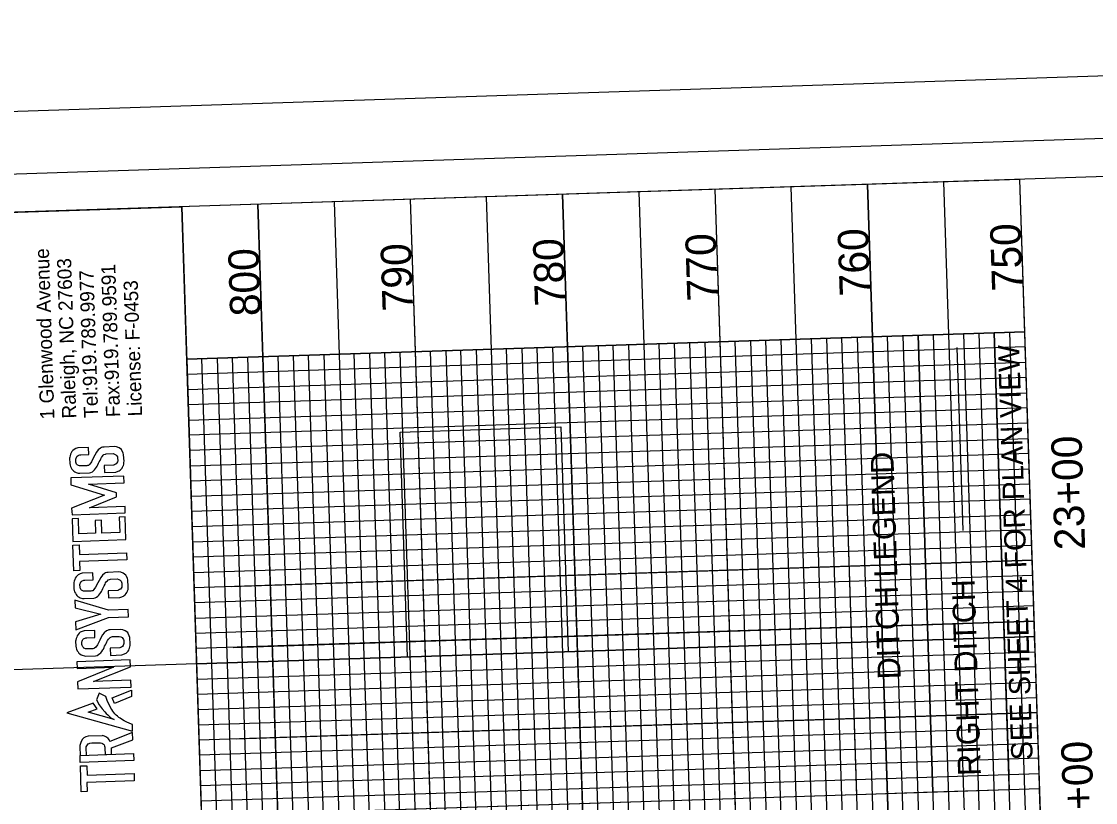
# Model space of a CAD drawing. Extents: x 1627314 to 1628469, y 762309 to 764212.
# Drawn here: x 1627512.6 to 1627864.9, y 763788.2 to 764044.4 of the extents above; entities that cross this region are included whole.
import ezdxf

# ---------------------------------------------------------------- set-up
doc = ezdxf.new("R2010")
doc.units = 0
for name, color, linetype in [('Exist Vertical Profile Horizontal Axis Label Major', 7, 'Continuous'), ('Exist Vertical Profile Vertical Axis Label', 7, 'Continuous'), ('Old_Level_2', 7, 'Continuous'), ('Old_Level_58', 7, 'Continuous'), ('Prop DSN Text', 7, 'Continuous'), ('Prop Grid Mask', 7, 'Continuous'), ('Prop PFL Ditch Label CELL', 7, 'Continuous'), ('Sheet DOT Grid CELL', 7, 'Continuous'), ('Sheet Layout Profile Border Port 1', 7, 'Continuous'), ('Sheet Plot Border Inside CELL', 7, 'Continuous'), ('Sheet Plot Border Outside CELL', 7, 'Continuous'), ('Sheet Profile CELL', 7, 'Continuous'), ('Sheet Profile Grid Major CELL', 7, 'Continuous'), ('Sheet Profile Grid Middle CELL', 7, 'Continuous'), ('Sheet Profile Grid Minor CELL', 7, 'Continuous')]:
    doc.layers.add(name, color=color, linetype=linetype)

msp = doc.modelspace()

# ---------------------------------------------------------------- linework, layer by layer
at = {"layer": 'Old_Level_2'}
for points in [[(1627534.7, 763902.32), (1627534.62, 763904.63), (1627531.15, 763904.51), (1627530.45, 763904.29), (1627529.87, 763903.99), (1627529.49, 763903.68), (1627529.15, 763903.3), (1627528.88, 763902.85), (1627528.72, 763902.42), (1627528.72, 763902.42), (1627528.54, 763901.95), (1627528.44, 763901.47), (1627528.37, 763901.14), (1627528.46, 763899.4), (1627528.57, 763898.87), (1627528.66, 763898.42), (1627528.92, 763897.96), (1627529.14, 763897.57), (1627529.44, 763897.18), (1627529.76, 763896.88), (1627530.13, 763896.65), (1627530.53, 763896.47), (1627531.24, 763896.24), (1627531.76, 763896.2), (1627534.92, 763896.31), (1627535.4, 763896.44), (1627535.88, 763896.68), (1627536.28, 763896.99), (1627536.58, 763897.29), (1627536.92, 763897.76), (1627537.25, 763898.22), (1627537.46, 763898.51), (1627537.67, 763899), (1627537.88, 763899.49), (1627538.12, 763899.89), (1627538.39, 763900.34), (1627538.64, 763900.87), (1627538.84, 763901.31), (1627539.14, 763901.75), (1627539.43, 763902.07), (1627539.66, 763902.33), (1627540.13, 763902.5), (1627540.43, 763902.6), (1627542.67, 763902.64), (1627543.16, 763902.5), (1627543.58, 763902.27), (1627543.88, 763901.95), (1627544.06, 763901.6), (1627544.14, 763901.26), (1627544.19, 763900.3), (1627544.11, 763899.97), (1627543.93, 763899.64), (1627543.75, 763899.3), (1627543.42, 763899.15), (1627543.09, 763899), (1627542.82, 763898.88), (1627539.71, 763898.74), (1627539.82, 763896.4), (1627543.52, 763896.57), (1627543.8, 763896.69), (1627544.65, 763896.99), (1627544.94, 763897.18), (1627545.25, 763897.44), (1627545.61, 763897.83), (1627545.8, 763898.14), (1627545.96, 763898.58), (1627546.03, 763898.74), (1627546.19, 763899.18), (1627546.23, 763899.72), (1627546.25, 763900.11), (1627546.13, 763902.25), (1627545.97, 763902.84), (1627545.57, 763903.65), (1627545.43, 763903.93), (1627544.62, 763904.52), (1627543.83, 763904.83), (1627543.11, 763904.96), (1627539.69, 763904.8), (1627539.22, 763904.77), (1627538.85, 763904.63), (1627538.5, 763904.43), (1627537.76, 763903.86), (1627537.23, 763903.14), (1627536.68, 763902.14), (1627536.26, 763901.39), (1627535.54, 763899.9), (1627535.01, 763899.13), (1627534.59, 763898.78), (1627534.31, 763898.7), (1627534.03, 763898.61), (1627531.6, 763898.58), (1627531.34, 763898.69), (1627531.08, 763898.81), (1627530.93, 763898.98), (1627530.72, 763899.21), (1627530.61, 763899.46), (1627530.49, 763899.72), (1627530.52, 763899.86), (1627530.44, 763899.88), (1627530.42, 763900.84), (1627530.53, 763901.12), (1627530.63, 763901.4), (1627530.73, 763901.68), (1627530.91, 763901.81), (1627531.19, 763902.01), (1627531.46, 763902.11), (1627531.73, 763902.21), (1627532.04, 763902.21)], [(1627539.83, 763888.95), (1627529.04, 763884.78), (1627529.22, 763882.58), (1627546.67, 763883.23), (1627546.59, 763885.34), (1627534.92, 763884.9), (1627543.79, 763888.46), (1627543.78, 763889.81), (1627534.56, 763892.58), (1627546.27, 763893), (1627546.19, 763895.28), (1627528.78, 763894.65), (1627528.86, 763892.35)], [(1627529.23, 763881.22), (1627529.48, 763873.84), (1627546.89, 763874.43), (1627546.64, 763881.9), (1627544.67, 763881.83), (1627544.84, 763876.79), (1627539, 763876.59), (1627538.86, 763880.8), (1627536.79, 763880.73), (1627536.93, 763876.49), (1627531.44, 763876.3), (1627531.27, 763881.31)], [(1627529.79, 763864.16), (1627529.51, 763872.62), (1627531.58, 763872.69), (1627531.69, 763869.58), (1627547.1, 763870.1), (1627547.18, 763867.75), (1627531.66, 763867.23), (1627531.76, 763864.26)], [(1627536.08, 763861.21), (1627536.01, 763863.52), (1627532.53, 763863.4), (1627531.83, 763863.18), (1627531.25, 763862.88), (1627530.87, 763862.57), (1627530.53, 763862.19), (1627530.26, 763861.74), (1627530.1, 763861.31), (1627530.1, 763861.31), (1627529.93, 763860.84), (1627529.82, 763860.36), (1627529.75, 763860.03), (1627529.84, 763858.29), (1627529.95, 763857.76), (1627530.04, 763857.31), (1627530.3, 763856.85), (1627530.52, 763856.46), (1627530.82, 763856.07), (1627531.14, 763855.77), (1627531.52, 763855.54), (1627531.92, 763855.36), (1627532.62, 763855.13), (1627533.14, 763855.09), (1627536.31, 763855.2), (1627536.78, 763855.33), (1627537.26, 763855.58), (1627537.67, 763855.88), (1627537.97, 763856.18), (1627538.3, 763856.65), (1627538.63, 763857.11), (1627538.84, 763857.4), (1627539.05, 763857.89), (1627539.26, 763858.38), (1627539.5, 763858.78), (1627539.77, 763859.23), (1627540.02, 763859.77), (1627540.23, 763860.21), (1627540.53, 763860.65), (1627540.81, 763860.96), (1627541.04, 763861.22), (1627541.52, 763861.39), (1627541.81, 763861.5), (1627544.05, 763861.53), (1627544.54, 763861.39), (1627544.97, 763861.16), (1627545.27, 763860.84), (1627545.44, 763860.49), (1627545.52, 763860.15), (1627545.57, 763859.19), (1627545.49, 763858.87), (1627545.31, 763858.53), (1627545.13, 763858.2), (1627544.8, 763858.04), (1627544.47, 763857.89), (1627544.21, 763857.77), (1627541.1, 763857.63), (1627541.2, 763855.29), (1627544.91, 763855.46), (1627545.19, 763855.58), (1627546.04, 763855.88), (1627546.32, 763856.07), (1627546.63, 763856.33), (1627547, 763856.72), (1627547.18, 763857.03), (1627547.35, 763857.48), (1627547.41, 763857.64), (1627547.58, 763858.07), (1627547.61, 763858.61), (1627547.64, 763859), (1627547.51, 763861.14), (1627547.35, 763861.73), (1627546.95, 763862.54), (1627546.82, 763862.82), (1627546.01, 763863.41), (1627545.21, 763863.72), (1627544.49, 763863.85), (1627541.08, 763863.69), (1627540.6, 763863.66), (1627540.23, 763863.52), (1627539.88, 763863.32), (1627539.14, 763862.75), (1627538.61, 763862.03), (1627538.06, 763861.04), (1627537.64, 763860.28), (1627536.92, 763858.79), (1627536.39, 763858.02), (1627535.98, 763857.67), (1627535.7, 763857.59), (1627535.42, 763857.5), (1627532.98, 763857.47), (1627532.73, 763857.58), (1627532.47, 763857.7), (1627532.31, 763857.87), (1627532.11, 763858.1), (1627531.99, 763858.35), (1627531.87, 763858.61), (1627531.9, 763858.75), (1627531.82, 763858.77), (1627531.81, 763859.73), (1627531.91, 763860.01), (1627532.01, 763860.29), (1627532.11, 763860.57), (1627532.3, 763860.7), (1627532.57, 763860.9), (1627532.84, 763861), (1627533.12, 763861.1), (1627533.42, 763861.1)], [(1627530.37, 763847.41), (1627530.45, 763844.88), (1627541.21, 763848.85), (1627547.75, 763849.09), (1627547.66, 763851.48), (1627541.17, 763851.24), (1627530.09, 763854.54), (1627530.24, 763852.05), (1627538.66, 763850.01)], [(1627536.72, 763842.35), (1627536.64, 763844.65), (1627533.16, 763844.54), (1627532.47, 763844.32), (1627531.89, 763844.02), (1627531.51, 763843.71), (1627531.17, 763843.33), (1627530.9, 763842.88), (1627530.74, 763842.45), (1627530.74, 763842.45), (1627530.56, 763841.98), (1627530.45, 763841.5), (1627530.38, 763841.17), (1627530.48, 763839.43), (1627530.59, 763838.9), (1627530.68, 763838.45), (1627530.93, 763837.99), (1627531.16, 763837.6), (1627531.46, 763837.21), (1627531.78, 763836.91), (1627532.15, 763836.68), (1627532.55, 763836.5), (1627533.26, 763836.27), (1627533.77, 763836.23), (1627536.94, 763836.34), (1627537.41, 763836.47), (1627537.9, 763836.71), (1627538.3, 763837.02), (1627538.6, 763837.32), (1627538.93, 763837.78), (1627539.27, 763838.25), (1627539.48, 763838.54), (1627539.69, 763839.03), (1627539.89, 763839.52), (1627540.13, 763839.92), (1627540.41, 763840.37), (1627540.66, 763840.9), (1627540.86, 763841.34), (1627541.16, 763841.78), (1627541.45, 763842.1), (1627541.68, 763842.36), (1627542.15, 763842.53), (1627542.45, 763842.63), (1627544.68, 763842.67), (1627545.17, 763842.53), (1627545.6, 763842.3), (1627545.9, 763841.98), (1627546.07, 763841.63), (1627546.16, 763841.29), (1627546.21, 763840.33), (1627546.13, 763840), (1627545.95, 763839.67), (1627545.76, 763839.33), (1627545.43, 763839.18), (1627545.1, 763839.03), (1627544.84, 763838.91), (1627541.73, 763838.77), (1627541.84, 763836.43), (1627545.54, 763836.6), (1627545.82, 763836.72), (1627546.67, 763837.02), (1627546.96, 763837.21), (1627547.27, 763837.47), (1627547.63, 763837.86), (1627547.81, 763838.17), (1627547.98, 763838.61), (1627548.04, 763838.77), (1627548.21, 763839.21), (1627548.25, 763839.75), (1627548.27, 763840.14), (1627548.15, 763842.28), (1627547.99, 763842.87), (1627547.59, 763843.68), (1627547.45, 763843.95), (1627546.64, 763844.55), (1627545.84, 763844.86), (1627545.13, 763844.99), (1627541.71, 763844.83), (1627541.24, 763844.8), (1627540.87, 763844.66), (1627540.52, 763844.46), (1627539.78, 763843.89), (1627539.24, 763843.17), (1627538.7, 763842.17), (1627538.28, 763841.42), (1627537.56, 763839.93), (1627537.02, 763839.15), (1627536.61, 763838.81), (1627536.33, 763838.73), (1627536.05, 763838.64), (1627533.62, 763838.61), (1627533.36, 763838.72), (1627533.1, 763838.84), (1627532.94, 763839.01), (1627532.74, 763839.23), (1627532.62, 763839.49), (1627532.51, 763839.75), (1627532.53, 763839.89), (1627532.46, 763839.91), (1627532.44, 763840.86), (1627532.54, 763841.15), (1627532.64, 763841.43), (1627532.74, 763841.71), (1627532.93, 763841.84), (1627533.2, 763842.04), (1627533.48, 763842.14), (1627533.75, 763842.24), (1627534.06, 763842.24)], [(1627531.1, 763825.45), (1627548.55, 763826.04), (1627548.47, 763828.28), (1627536.2, 763827.86), (1627548.35, 763832.72), (1627548.25, 763834.96), (1627530.75, 763834.37), (1627530.83, 763832.19), (1627542.8, 763832.6), (1627531.01, 763827.81)], [(1627527.54, 763817.56), (1627549.08, 763811.6), (1627548.99, 763813.82), (1627548.14, 763814.14), (1627546.97, 763814.67), (1627546.33, 763814.96), (1627545.78, 763815.32), (1627545, 763815.82), (1627544.52, 763816.13), (1627544.12, 763816.5), (1627543.71, 763816.86), (1627543.2, 763817.33), (1627542.92, 763817.74), (1627542.57, 763818.14), (1627542.23, 763818.69), (1627541.93, 763819.17), (1627541.33, 763820.37), (1627540.88, 763821.35), (1627540.27, 763822.98), (1627538.09, 763824.04), (1627537.21, 763821.84), (1627538.15, 763820.23), (1627539.1, 763818.89), (1627539.92, 763817.93), (1627540.37, 763817.42), (1627540.95, 763816.91), (1627541.54, 763816.39), (1627541.97, 763816.01), (1627542.63, 763815.65), (1627543, 763815.45), (1627534.54, 763817.81), (1627537.4, 763818.9), (1627536.08, 763820.75)], [(1627543.15, 763820.69), (1627542.32, 763822.58), (1627548.68, 763825.05), (1627548.67, 763822.95)], [(1627533.93, 763803.74), (1627533.85, 763806.13), (1627533.89, 763806.43), (1627534.04, 763806.84), (1627534.24, 763807.17), (1627534.51, 763807.41), (1627534.83, 763807.58), (1627535.09, 763807.71), (1627535.67, 763807.73), (1627538.16, 763807.82), (1627538.49, 763807.77), (1627538.94, 763807.7), (1627539.23, 763807.58), (1627539.5, 763807.38), (1627539.72, 763807.12), (1627539.89, 763806.7), (1627539.94, 763806.38), (1627539.99, 763806.05), (1627540.07, 763803.95), (1627542.18, 763804.03), (1627542.1, 763806.13), (1627549.18, 763808.74), (1627549.07, 763811.15), (1627541.63, 763808.25), (1627541.48, 763808.63), (1627541.06, 763809.15), (1627540.51, 763809.62), (1627539.87, 763809.95), (1627539.23, 763810.14), (1627539.04, 763810.12), (1627534.48, 763810.01), (1627533.74, 763809.79), (1627533.08, 763809.4), (1627532.62, 763808.98), (1627532.17, 763808.26), (1627531.96, 763807.58), (1627531.76, 763806.89), (1627531.77, 763806.49), (1627531.84, 763803.67)], [(1627531.92, 763801.36), (1627531.84, 763803.67), (1627549.4, 763804.26), (1627549.48, 763801.95)], [(1627532.23, 763791.74), (1627531.95, 763800.2), (1627534.02, 763800.27), (1627534.12, 763797.16), (1627549.54, 763797.68), (1627549.62, 763795.33), (1627534.1, 763794.81), (1627534.2, 763791.84)]]:
    msp.add_lwpolyline(points, close=True, dxfattribs=at)
at = {"layer": 'Old_Level_58'}
msp.add_lwpolyline([(1627507.79, 763781.55), (1627501.25, 763981.49), (1627565.16, 763983.58), (1627571.7, 763783.64)], close=True, dxfattribs=at)
at = {"layer": 'Prop Grid Mask'}
for points in [[(1627811.57, 763791.55), (1627806.67, 763941.47), (1627831.66, 763942.29), (1627836.56, 763792.37)], [(1627831.66, 763942.29), (1627836.4, 763797.36), (1627846.39, 763797.69), (1627841.65, 763942.61)], [(1627786.59, 763790.73), (1627781.68, 763940.65), (1627806.67, 763941.47), (1627811.57, 763791.55)], [(1627639.21, 763835.85), (1627636.79, 763909.68), (1627689.5, 763911.4), (1627691.91, 763837.57)]]:
    msp.add_lwpolyline(points, close=True, dxfattribs=at)
at = {"layer": 'Prop PFL Ditch Label CELL'}
for p, q in [((1627821.42, 763877.47), (1627819.46, 763937.43)), ((1627821.42, 763877.47), (1627819.46, 763937.43)), ((1627826.56, 763792.04), (1627826.56, 763792.04))]:
    msp.add_line(p, q, dxfattribs=at)
at = {"layer": 'Sheet DOT Grid CELL'}
for p, q in [((1627740.07, 763989.32), (1627789.11, 762490.12)), ((1627790.04, 763990.95), (1627839.08, 762491.75)), ((1627590.15, 763984.41), (1627639.19, 762485.21)), ((1627640.12, 763986.05), (1627689.16, 762486.85)), ((1627690.1, 763987.68), (1627739.13, 762488.48)), ((1627841.65, 763942.61), (1627566.8, 763933.62)), ((1627843.28, 763892.64), (1627568.43, 763883.65)), ((1627844.92, 763842.67), (1627570.07, 763833.68)), ((1627846.55, 763792.69), (1627484.3, 763780.84))]:
    msp.add_line(p, q, dxfattribs=at)
at = {"layer": 'Sheet Layout Profile Border Port 1'}
msp.add_lwpolyline([(1627386.05, 762576.99), (1627885.78, 762593.33), (1627841.65, 763942.61), (1627566.8, 763933.62), (1627570.07, 763833.63), (1627345.19, 763826.32)], close=True, dxfattribs=at)
msp.add_lwpolyline([(1627548.65, 762532.28), (1627887.42, 762543.36), (1627841.65, 763942.61), (1627566.8, 763933.62)], dxfattribs=at)
at = {"layer": 'Sheet Plot Border Inside CELL'}
msp.add_lwpolyline([(1628446.34, 762357.53), (1628391.86, 764023.14), (1627337.33, 763988.65), (1627391.81, 762323.04)], close=True, dxfattribs=at)
at = {"layer": 'Sheet Plot Border Outside CELL'}
msp.add_lwpolyline([(1628469.21, 762345.27), (1628413.63, 764044.37), (1627314.22, 764008.4), (1627369.79, 762309.31)], close=True, dxfattribs=at)
at = {"layer": 'Sheet Profile CELL'}
msp.add_line((1627889.05, 762493.39), (1627840.02, 763992.59), dxfattribs=at)
msp.add_lwpolyline([(1627340.28, 763976.24), (1627389.32, 762477.04), (1628438.76, 762511.37), (1628389.72, 764010.57)], close=True, dxfattribs=at)
at = {"layer": 'Sheet Profile Grid Major CELL'}
for points in [[(1627566.8, 763933.62), (1627841.65, 763942.61), (1627840.02, 763992.59), (1627490.2, 763981.14)], [(1627740.07, 763989.32), (1627789.11, 762490.12), (1627789.11, 762490.12), (1627839.08, 762491.75), (1627790.04, 763990.95)], [(1627546.71, 763782.88), (1627589.21, 762483.58), (1627639.19, 762485.21), (1627590.15, 763984.41)], [(1627640.12, 763986.05), (1627689.16, 762486.85), (1627739.13, 762488.48), (1627690.1, 763987.68)], [(1627570.07, 763833.68), (1627844.92, 763842.67), (1627843.28, 763892.64), (1627843.28, 763892.64), (1627568.43, 763883.65)], [(1627861.27, 763342.93), (1627859.63, 763392.91), (1627359.9, 763376.56), (1627358.26, 763426.53), (1627858, 763442.88), (1627856.36, 763492.85), (1627356.63, 763476.51), (1627354.99, 763526.48), (1627854.73, 763542.83), (1627853.09, 763592.8), (1627353.36, 763576.45), (1627351.73, 763626.43), (1627851.46, 763642.77), (1627849.82, 763692.75), (1627350.09, 763676.4), (1627348.46, 763726.37), (1627848.19, 763742.72), (1627846.55, 763792.69), (1627346.82, 763776.35), (1627345.96, 763802.63)]]:
    msp.add_lwpolyline(points, dxfattribs=at)
at = {"layer": 'Sheet Profile Grid Middle CELL'}
for points in [[(1627815.03, 763991.77), (1627864.07, 762492.57)], [(1627715.08, 763988.5), (1627764.12, 762489.3), (1627814.09, 762490.94), (1627765.06, 763990.13)], [(1627615.14, 763985.23), (1627664.17, 762486.03), (1627714.15, 762487.67), (1627665.11, 763986.86)], [(1627570.88, 763808.69), (1627565.16, 763983.6)], [(1627581.44, 763859.06), (1627844.1, 763867.65), (1627842.47, 763917.63), (1627567.61, 763908.64)], [(1627583.08, 763809.09), (1627845.74, 763817.68), (1627844.1, 763867.65), (1627569.25, 763858.66)], [(1627360.72, 763351.57), (1627860.45, 763367.92), (1627858.81, 763417.89), (1627359.08, 763401.55), (1627357.45, 763451.52), (1627857.18, 763467.87), (1627855.54, 763517.84), (1627355.81, 763501.49), (1627354.18, 763551.47), (1627853.91, 763567.81), (1627852.28, 763617.79), (1627352.54, 763601.44), (1627350.91, 763651.41), (1627850.64, 763667.76), (1627849.01, 763717.73), (1627349.27, 763701.39), (1627347.64, 763751.36), (1627847.37, 763767.71), (1627845.74, 763817.68), (1627570.88, 763808.69)], [(1627521.73, 763782.02), (1627564.23, 762482.76), (1627614.2, 762484.4), (1627570.88, 763808.69)]]:
    msp.add_lwpolyline(points, dxfattribs=at)
at = {"layer": 'Sheet Profile Grid Minor CELL'}
for p, q in [((1627867.43, 762542.71), (1627821.66, 763941.96)), ((1627826.66, 763942.12), (1627872.43, 762542.87)), ((1627877.42, 762543.03), (1627831.66, 763942.29)), ((1627767.48, 762539.44), (1627721.71, 763938.69)), ((1627726.71, 763938.85), (1627772.48, 762539.6)), ((1627731.71, 763939.02), (1627777.48, 762539.76)), ((1627736.71, 763939.18), (1627782.48, 762539.93)), ((1627792.47, 762540.25), (1627746.7, 763939.51)), ((1627751.7, 763939.67), (1627797.47, 762540.42)), ((1627802.47, 762540.58), (1627756.7, 763939.83)), ((1627761.69, 763940), (1627807.46, 762540.75)), ((1627817.46, 762541.07), (1627771.69, 763940.32)), ((1627776.69, 763940.49), (1627822.45, 762541.24)), ((1627827.45, 762541.4), (1627781.68, 763940.65)), ((1627786.68, 763940.81), (1627832.45, 762541.56)), ((1627842.44, 762541.89), (1627796.67, 763941.14)), ((1627801.67, 763941.3), (1627847.44, 762542.05)), ((1627852.44, 762542.22), (1627806.67, 763941.47)), ((1627811.67, 763941.63), (1627857.44, 762542.38)), ((1627652.55, 762535.68), (1627606.78, 763934.93)), ((1627611.77, 763935.09), (1627657.54, 762535.84)), ((1627667.54, 762536.17), (1627621.77, 763935.42)), ((1627626.77, 763935.58), (1627672.53, 762536.33)), ((1627677.53, 762536.5), (1627631.76, 763935.75)), ((1627636.76, 763935.91), (1627682.53, 762536.66)), ((1627692.52, 762536.99), (1627646.75, 763936.24)), ((1627651.75, 763936.4), (1627697.52, 762537.15)), ((1627702.52, 762537.31), (1627656.75, 763936.56)), ((1627661.75, 763936.73), (1627707.52, 762537.48)), ((1627717.51, 762537.8), (1627671.74, 763937.05)), ((1627676.74, 763937.22), (1627722.51, 762537.97)), ((1627727.51, 762538.13), (1627681.74, 763937.38)), ((1627686.73, 763937.55), (1627732.5, 762538.29)), ((1627742.5, 762538.62), (1627696.73, 763937.87)), ((1627701.73, 763938.04), (1627747.49, 762538.78)), ((1627752.49, 762538.95), (1627706.72, 763938.2)), ((1627711.72, 763938.36), (1627757.49, 762539.11)), ((1627576.79, 763933.95), (1627622.56, 762534.7)), ((1627627.56, 762534.86), (1627581.79, 763934.11)), ((1627586.79, 763934.28), (1627632.56, 762535.02)), ((1627642.55, 762535.35), (1627596.78, 763934.6)), ((1627601.78, 763934.77), (1627647.55, 762535.51))]:
    msp.add_line(p, q, dxfattribs=at)
for points in [[(1627836.65, 763942.45), (1627882.42, 762543.2)], [(1627567.12, 763923.63), (1627841.98, 763932.62), (1627841.81, 763937.62), (1627566.96, 763928.62)], [(1627566.71, 763783.49), (1627607.57, 762534.21), (1627617.56, 762534.53), (1627571.79, 763933.79)], [(1627567.45, 763913.63), (1627842.3, 763922.62), (1627842.14, 763927.62), (1627567.29, 763918.63)], [(1627567.94, 763898.64), (1627842.79, 763907.63), (1627842.63, 763912.63), (1627567.78, 763903.64)], [(1627568.27, 763888.65), (1627843.12, 763897.64), (1627842.96, 763902.63), (1627568.1, 763893.64)], [(1627568.76, 763873.65), (1627843.61, 763882.64), (1627843.45, 763887.64), (1627568.6, 763878.65)], [(1627569.09, 763863.66), (1627843.94, 763872.65), (1627843.78, 763877.65), (1627568.92, 763868.66)], [(1627569.58, 763848.67), (1627844.43, 763857.66), (1627844.27, 763862.66), (1627569.41, 763853.66)], [(1627582.1, 763839.07), (1627844.76, 763847.66), (1627844.59, 763852.66), (1627569.74, 763843.67)], [(1627570.23, 763828.65), (1627845.04, 763837.57), (1627844.87, 763842.56), (1627844.76, 763847.66), (1627569.9, 763838.67)], [(1627570.72, 763813.69), (1627845.57, 763822.68), (1627845.57, 763822.68), (1627845.41, 763827.67), (1627845.25, 763832.67), (1627570.39, 763823.68)], [(1627570.56, 763818.68), (1627845.41, 763827.67)], [(1627571.21, 763798.69), (1627846.06, 763807.68), (1627845.9, 763812.68), (1627571.05, 763803.69)], [(1627571.54, 763788.7), (1627846.39, 763797.69), (1627846.23, 763802.69), (1627571.37, 763793.7)]]:
    msp.add_lwpolyline(points, dxfattribs=at)

# ---------------------------------------------------------------- texts
at = {"layer": 'Exist Vertical Profile Horizontal Axis Label Major'}
for s, p in [('23+00', (1627861.5, 763871.16)), ('22+00', (1627864.77, 763771.05))]:
    msp.add_text(s, height=10, rotation=91.8735, dxfattribs=at).set_placement(p)
at = {"layer": 'Exist Vertical Profile Vertical Axis Label'}
for s, p in [('750', (1627840.96, 763956.03)), ('770', (1627741.01, 763952.76)), ('760', (1627790.99, 763954.39)), ('790', (1627641.07, 763949.49)), ('780', (1627691.04, 763951.13)), ('800', (1627591.09, 763947.86))]:
    msp.add_text(s, height=10, rotation=91.8735, dxfattribs=at).set_placement(p)
at = {"layer": 'Old_Level_2'}
for s, p in [('1 Glenwood Avenue', (1627523.43, 763913.98)), ('Raleigh, NC 27603', (1627530.62, 763914.21)), ('Fax:919.789.9591', (1627545.01, 763914.68)), ('Tel:919.789.9977 ', (1627537.81, 763914.45)), ('License: F-0453', (1627552.2, 763914.92))]:
    msp.add_text(s, height=4.6576, rotation=91.8735, dxfattribs=at).set_placement(p)
at = {"layer": 'Prop DSN Text'}
msp.add_text('SEE SHEET 4 FOR PLAN VIEW', height=7, rotation=91.8735, dxfattribs=at).set_placement((1627844.29, 763802.2))
at = {"layer": 'Prop PFL Ditch Label CELL'}
for s, height, p in [('DITCH LEGEND', 7.5, (1627801, 763828.72)), ('RIGHT DITCH', 7.485, (1627827.3, 763797.07))]:
    msp.add_text(s, height=height, rotation=91.8735, dxfattribs=at).set_placement(p)

doc.saveas('drawing.dxf')
